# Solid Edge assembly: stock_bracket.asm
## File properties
Author: Deepak Maini
Template: Normal.asm
Last saved by: MYPC
Revision: 25
Application: Solid Edge
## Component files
adjusting_screw_guide.par
adjusting_nut_handle.par
stock_support_roller.par
Stock_support_base.par
thrust_bearing.par
adjusting_screw_nut.par
support_adjusting_screw.par
support_roller_bracket.par
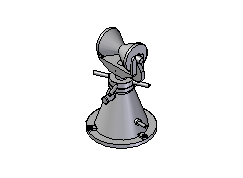
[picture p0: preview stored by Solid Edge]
